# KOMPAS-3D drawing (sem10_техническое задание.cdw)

Views: Вид 1
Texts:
  Автопилот стабилизации угла крена
  Техническое задание
  Hornet
  1. Конструкторская часть.
  Разработать боковой канал системы автоматического управления
  самолетом, используя следующую информацию:
  Режимы полета ЛА
  Режим
  Н, км
  Коэффициенты линейной модели
  Реж
  Использовать сервопривод с жесткой обратной связью
  Требуемые характеристики переходных процессов
  1. Автопилот крена
  а) время регулирования t рег =2..5 с
  б) перерегулирование  <5%
  в) статическая ошибка  <5%
  2. Автопилот курса перекрестной схемы
  а) время регулирования t рег =10..18 с
  б) перерегулирование  3%
  Условия эксплуатации
  а) диапозон изменения температуры окружающей среды -60..+60 о С;
  б) относительная влажность воздуха 98% при 40 о С;
  в) ударные нагрузки до 8 в течение 15с;
  г) вибрации с амплитудой 5мм и частотой 5..40 Гц.
  2. Технологическая часть
  Разработать установку для проверки параметров рулевых машин
  Полетная область ЛА
  Н, мх10 3
  Пашинин С.А.
  Окоемов Б.Н.
  МГТУ им. Н.Э.Баумана
  Кафедра ИУ2
  Группа ИУ2-102
  Автопилот крена-
Dimensions and other numbers on the sheet: 1; 0; 0,4; 2; 0,8; 3; 1,2; 4; 5; 1,6; 6; 10; 7; 1,5; 8; 9; 15; 11; 12; 20; 2,35; 0,635; 5,47; 2,72; 0,269; 3,26; 0,709; 0,043; 3,1; 20,2; 17,6; 0,0719; -0,518; 0,0571; 0,0649; 1,38; 25,5; 9,2; 0,527; 13,1; 1,13; 0,0709; 7,32; 61,7; 51,2; 0,,036; -3,03; 0,126; 0,0134; 2,5; 54,4; 10,6; 0,905; 10,4; 0,0554; 12,6; 176; 33,5; 0,024; -1,95; 0,178; 0,0016; 0,354; 2,75; 1,51; 0,153; 1,49; 0,525; 0,0254; 1,79; 13,9; 9,78; 0,0759; -0,313; 0,0085; 0,125; 1,64; 40; 7,56; 0,62; 7,36; 0,985; 0,0278; 7,23; 138; 22,9; 0,0191; 1,05; 0,131; 0,0044; 0,405; 6,41; 2,88; 0,159; 3,5; 0,443; 2,2; 19,2; 0,0409; -1,11; 0,033; 0,0541; 0,857; 18; 4,79; 0,312; 4,45; 0,551; 0,0203; 3,8; 65,5; 17; 0,0218; -0,187; 0,0773; 0,0136; 0,894; 21,7; 4,23; 0,371; 5,25; 0,556; 0,0139; 3,92; 78,7; 15,9; 0,0164; -0,297; 0,0812; 0,0099; 0,184; 2,77; 1,35; 0,0738; 1,36; 0,276; 0,0121; 1,04; 12,9; 8,86; 0,0413; -0,176; 0,004; 0,117; 0,395; 0,506; 0,15; 7,92; 2,03; 2,48; 2,1; 0,813; 0,146; 0,187; 0,0602; 2,23; 3,13; 0,816; 0,302; 0,305; 0,148; 0,0107; 0,0067; 0,0027; 1,77; 1,82; 30,8; 44,3; 14,4; 9,84; 4,2; 0,0222; 0,0141; 0,0166; -0,378; 0,0306; -0,042; 0,0372; 0,0345; 0,0422; 0,0216; 0,0776; 21; 24; 0,5; 27; 1:1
